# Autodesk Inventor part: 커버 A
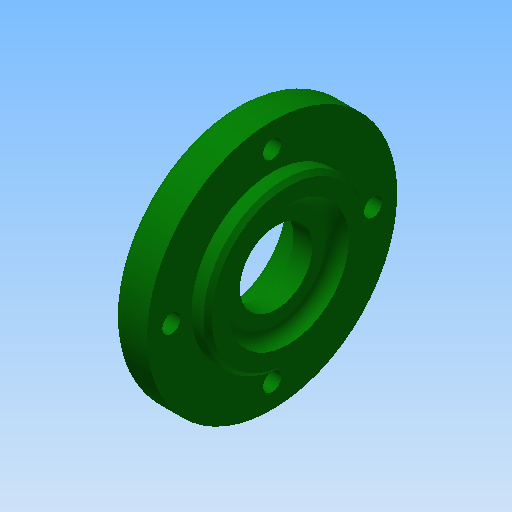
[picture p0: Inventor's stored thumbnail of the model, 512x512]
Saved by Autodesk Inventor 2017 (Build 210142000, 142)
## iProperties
Created: 2019-01
Part Number: 커버 A
Material: 알루미늄 6061
Document SubType Name: Modeling
Designer: mduedu
Density: 2.71 g/cm^3
Appearance: 진녹색
Mass: 67.6006 g
Surface Area: 94.463 cm^2
Volume: 24.9449 cm^3
Author: mduedu
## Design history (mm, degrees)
sketch "스케치1"
  geometry: L1 (0, 0)-(9, 0); L2 (9, 0)-(9, 31); L3 (9, 31)-(0, 31); L4 (0, 31)-(0, 0); L5 (9, 0)-(13, 0); L6 (13, 0)-(13, 20); L7 (13, 20)-(9, 20); L8 (9, 20)-(9, 0)
  constraints: 16 end point, 4 parallel, 2 horizontal, 2 perpendicular
  dimensions: "d0" = 13 distance between parallel lines of L6 L4; "d2" = 62 diameter of L3 L1; "d3" = 40 diameter of L7 L5; "d4" = 4 distance between parallel lines of L6 L2
revolve "회전1" sketch "스케치1" stored, may be unused: angle "d5" = 90 deg
sketch "스케치5"
  geometry: C1 r 19 at (0, 0); 1 further point
  constraints: 1 centre point, 1 coincident
  dimensions: "d34" = 38 diameter of C1
extrude "돌출1" join sketch "스케치5" distance "d35" = 3; taper "d36" = 0 deg
sketch "스케치2"
  geometry: L1 (9, -20)-(9, -31) reference; L2 (9, -31)-(0, -31) reference; L3 (0, -31)-(0, -19) reference; L4 (0, -19)-(-3, -19) reference; L5 (-3, -19)-(-3, 19) reference; L6 (-3, 19)-(0, 19) reference; L7 (0, 19)-(0, 31) reference; L8 (0, 31)-(9, 31) reference; L9 (9, 31)-(9, 20) reference; L10 (9, 20)-(13, 20) reference; L11 (13, 20)-(13, -20) reference; L12 (13, -20)-(9, -20) reference; L13 (-3, 0)-(5.3, 0); L14 (5.3, 0)-(5.3, 15); L15 (5.3, 15)-(-3, 15); L16 (-3, 15)-(-3, 0); L17 (5.3, 0)-(10, 0); L18 (10, 0)-(10, 9); L19 (10, 9)-(5.3, 9); L20 (5.3, 9)-(5.3, 0); L21 (10, 0)-(13, 0); L22 (13, 0)-(13, 15); L23 (13, 15)-(10, 15); L24 (10, 15)-(10, 0)
  constraints: 24 end point, 6 parallel, 3 horizontal, 3 perpendicular, 1 midpoint, 1 point on line
  dimensions: "d38" = 30 diameter of L15 L13; "d40" = 30 diameter of L23 L21; "d41" = 3 distance of L22.end L23.end; "d42" = 8.3 distance of L14.end L15.end; "d43" = 18 diameter of L19 L17
revolve "회전2" sketch "스케치2" stored, may be unused: angle "d12" = 90 deg
chamfer "모따기1" distance "d13" = 0.8; stored, may be unused: second distance "d14" = 2, angle "d15" = 30 deg
fillet "모깎기1" dims "d16" = 0.5
fillet "모깎기2" dims "d17" = 3
fillet "모깎기3" dims "d18" = 3
chamfer "모따기2" distance "d24" = 1; stored, may be unused: second distance "d25" = 2, angle "d26" = 45 deg
sketch "스케치3" dims "d19" = 50
  geometry: 6 further points
  constraints: 2 vertical alignment, 1 coincident, 7 other
  dimensions: "d22" = 360 deg dimension on point (0, 0) point (0, 25) (derived)
sketch "스케치4"
  geometry: 4 further points
  constraints: 4 other
hole "구멍1" sketch "스케치4" at (-25, 0), (0, -25), (25, 0), (0, 25) diameter "d27" = 4.5; stored, may be unused: countersink angle "d31" = 90 deg, drill point angle "d33" = 0 deg; dims "d28" = 6, "d29" = 8, "d30" = 4.6, "d32" = 8
fillet "모깎기6" dims "d47" = 1
node "솔리드1"
node "절단 모서리 투영2"
